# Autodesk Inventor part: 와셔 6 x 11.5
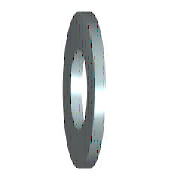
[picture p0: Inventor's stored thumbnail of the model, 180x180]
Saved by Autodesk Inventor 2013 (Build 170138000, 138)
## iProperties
IsCustomPart: 1
Created: 2012-02
Part Number: 와셔 6 x 11.5
Material: 강철, 연강
Description: 평면 와셔
Document SubType Name: Modeling
Standard: KS B 1326
Designer: mduedu
Standards Organization: KS
Language: ko-KR
Size Designation: 6x11.5
Categories: <MemberInstance><Categories><Category DisplayName="조임쇠" InternalName="e4da775c-781d-43d5-af7c-5136215cf5a6" Mnemonic="FSTN"><Category DisplayName="와셔" InternalN
Density: 7.86 g/cm^3
Mass: 0.901687 g
Surface Area: 2.33373 cm^2
Volume: 0.114718 cm^3
Author: mduedu
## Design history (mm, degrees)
sketch "스케치"
  geometry: C1 r 5.75 at (0, 0); C2 r 3.2 at (0, 0); 1 further point
  constraints: 2 centre point, 2 coincident
  dimensions: "d0" = 6.4 diameter of C2 (= SD1); "d1" = 11.5 diameter of C1 (= SD2)
extrude "본체" new body sketch "스케치" distance "d2" = 1.6 (= SD); taper "d3" = 0 deg
workaxis "Work Axis1"
workplane "Work Plane1"
body "Solid1"
other parameters: "SD1" = 6.4 [user parameter; used in 1 equation term], "SD2" = 11.5 [user parameter; used in 1 equation term], "SD" = 1.6 [user parameter; used in 1 equation term], "d4" = 0, "d5" = 0, "d6" = 0, "d7" = 0, "NND" = 6 [user parameter]
